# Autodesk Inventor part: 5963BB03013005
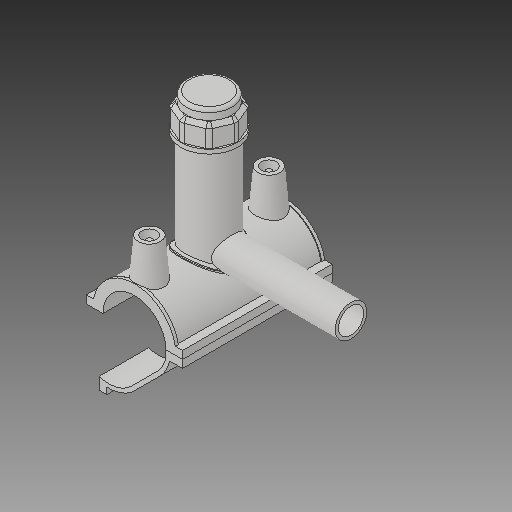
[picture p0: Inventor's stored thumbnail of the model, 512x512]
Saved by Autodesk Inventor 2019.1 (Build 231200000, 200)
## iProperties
Created: 2017-07
Part Number: 5963BB03013005
Material: Generic
Description: PLASSON TAPPING SADDLE 1 1/4''IPS x 1/2''IPS
Document SubType Name: Modeling
Designer: KIM
Mass: 1712.7 g
Surface Area: 2671.49 cm^2
Volume: 1712.7 cm^3
Density: 1 g/cm^3
Appearance: Default
Author: KIM
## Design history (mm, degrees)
derived "5963B.ipt"
feature "Solid1::5963B.ipt"
feature "Solid2::5963B.ipt"
feature "Solid4::5963B.ipt"
feature "Solid5::5963B.ipt"
tag "TaggingFeature1"
body "Solid1"
body "Solid2"
other parameters: "d_" = 42.1, "B_" = 64.516, "L_" = 100.076, "d_t" = 6, "H_2" = 93.726, "H_1" = 7.874, "d_1" = 21.2, "H_" = 94.996, "d1" = 54.73, "d148" = 0.6315, "d160" = 0.6315, "d169" = 3.2805, "d192" = 6.1236, "d0" = 42.1, "d2" = 64.516, "d3" = 10.525, "d4" = 100.076, "d5" = 0, "d6" = 0.1, "d8" = 0, "d19" = 6, "d20" = 6, "d21" = 60.0456, "d23" = 0, "d24" = 30.0228, "d26" = 0, "d29" = 3, "d30" = 14.03333, "d31" = 6, "d32" = 0, "d33" = 0, "d34" = 0.6, "d40" = 28.4596, "d41" = 37.89, "d43" = 0, "d45" = 0, "d47" = 87.4106, "d70" = 15, "d72" = 0, "d73" = 6, "d75" = 5, "d76" = 0, "d77" = 2.105, "d78" = 51.05, "d79" = 15, "d80" = 40.0304, "d82" = 5 deg, "d84" = 4, "d85" = 14, "d86" = 0, "d87" = 3, "d88" = 0, "d89" = 1, "d90" = 1, "d91" = 80.0608, "d92" = 0, "d93" = 0.5, "d94" = 22.15789, "d96" = 55.8246, "d97" = 2.00152, "d98" = 0, "d102" = 0.421, "d120" = 140 deg, "d121" = 24.228, "d122" = 20 deg, "d123" = 109.46, "d124" = 32.838, "d126" = 0, "d143" = 43.363, "d145" = 9.71538, "d149" = 0.6315, "d150" = 10.68692, "d153" = 100.076, "d154" = 0, "d156" = 27.365, "d157" = 160 deg, "d159" = 2.526, "d161" = 0.6315, "d162" = 60.0456, "d163" = 0, "d164" = 21.05, "d167" = 4.21, "d168" = 26.69756, "d170" = 3.2805, "d172" = 0, "d173" = 1, "d175" = 21.05, "d176" = 20 deg, "d177" = 2.947, "d178" = 12.63, "d180" = 0, "d183" = 5.052, "d184" = 2.3576, "d185" = 32.5247, "d186" = 32.5247, "d187" = 27.365, "d188" = 3.789, "d189" = 2.947, "d190" = 0, "d191" = 41.0475, "d193" = 6.1236, "d194" = 3.50266, "d195" = 90 deg, "d197" = 0, "d199" = 0, "d200" = 6.315, "d202" = 0, "d203" = 93.726, "d204" = 35.9955, "d205" = 26.523, "d206" = 32.2065, "d207" = 70.2945, "d208" = 73.10628, "d209" = 87.16518, "d210" = 32.5854, "d211" = 37.89, "d212" = 30.312, "d213" = -2.4534, "d216" = 0, "d217" = 4.21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
